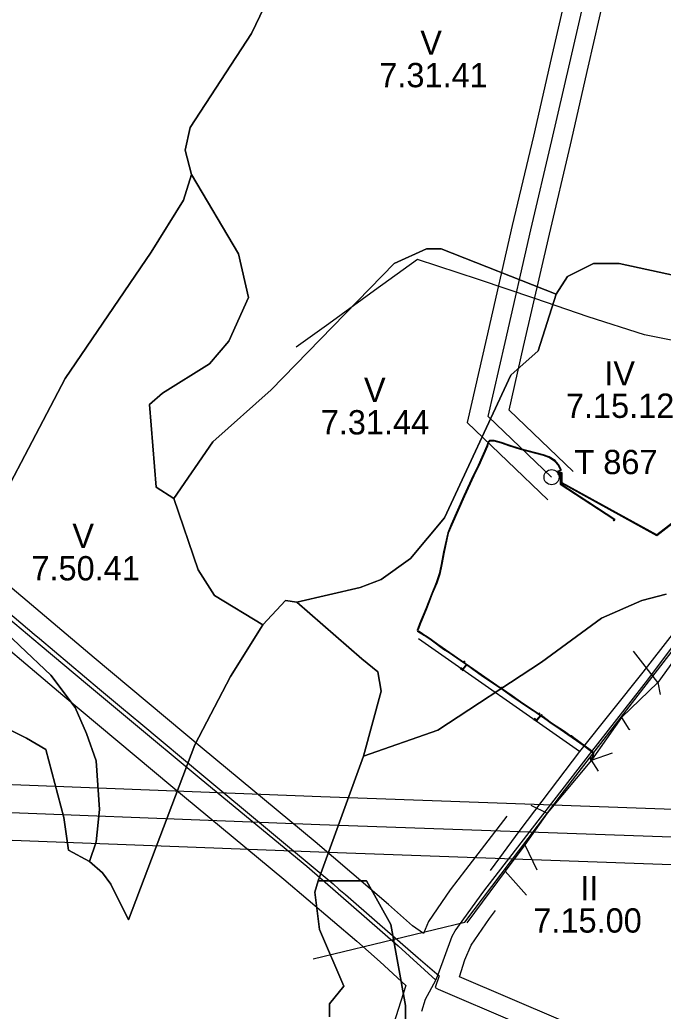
# Model space of a CAD drawing. Extents: x -694504 to -690518, y -983661 to -978958.
# Drawn here: x -692818 to -692421, y -982051 to -981439 of the extents above; entities that cross this region are included whole.
import ezdxf

# ---------------------------------------------------------------- set-up
doc = ezdxf.new("R2010")
doc.units = 0
for name, color, linetype in [('BPEJ', 7, 'Continuous'), ('kabelové a venkovní rozvody telefonu', 7, 'Continuous'), ('kanalizace', 7, 'Continuous'), ('ochranné pásmo silnic', 7, 'Continuous'), ('ochranné pásmo vedení', 7, 'Continuous'), ('PŘÍRODNÍ PARK JEŠTĚD', 7, 'Continuous'), ('trafostanice', 7, 'Continuous'), ('třídy přednosti v ochraně ZP', 7, 'Continuous'), ('vedení NN', 7, 'Continuous'), ('vedení VN 35kV', 7, 'Continuous'), ('vedení VVN 110kV', 7, 'Continuous'), ('vodovodní řad', 7, 'Continuous')]:
    doc.layers.add(name, color=color, linetype=linetype)

msp = doc.modelspace()

# ---------------------------------------------------------------- linework, layer by layer
at = {"layer": 'BPEJ'}
for points in [[(-692662.4, -981420.81), (-692675.4, -981447.81), (-692713.4, -981505.81), (-692716.4, -981519.81), (-692712.4, -981534.81), (-692717.4, -981550.81), (-692737.4, -981582.81), (-692790.4, -981660.81), (-692849.4, -981772.81)], [(-692374.4, -981605.81), (-692448.4, -981589.81), (-692464.4, -981589.81), (-692480.4, -981597.81), (-692487.4, -981608.81), (-692558.4, -981580.81), (-692567.4, -981580.81), (-692587.4, -981589.81), (-692663.4, -981667.81), (-692699.4, -981699.81), (-692723.4, -981734.81), (-692734.4, -981727.81), (-692738.4, -981676.81), (-692730.4, -981669.81), (-692701.4, -981651.81), (-692689.4, -981637.81), (-692677.4, -981610.81), (-692683.4, -981583.81), (-692712.4, -981534.81), (-692716.4, -981519.81), (-692713.4, -981505.81), (-692675.4, -981447.81), (-692662.4, -981420.81)], [(-692849.4, -981772.81), (-692790.4, -981660.81), (-692737.4, -981582.81), (-692717.4, -981550.81), (-692712.4, -981534.81), (-692683.4, -981583.81), (-692677.4, -981610.81), (-692689.4, -981637.81), (-692701.4, -981651.81), (-692730.4, -981669.81), (-692738.4, -981676.81), (-692734.4, -981727.81), (-692723.4, -981734.81), (-692723.4, -981734.81), (-692708.4, -981778.81), (-692698.4, -981794.81), (-692668.4, -981812.81), (-692688.4, -981844.81), (-692710.4, -981886.81), (-692751.4, -981994.81), (-692762.4, -981972.81), (-692767.4, -981965.81), (-692775.4, -981958.81), (-692771.4, -981946.81), (-692769.4, -981926.81), (-692771.4, -981896.81), (-692777.4, -981879.81), (-692784.4, -981863.81), (-692799.4, -981843.81), (-692818.4, -981825.81), (-692838.4, -981806.81)], [(-692419.4, -981793.81), (-692434.4, -981797.81), (-692459.4, -981808.81), (-692496.4, -981835.81), (-692560.4, -981877.81), (-692606.4, -981893.81), (-692595.4, -981853.81), (-692597.4, -981841.81), (-692607.4, -981833.81), (-692647.4, -981798.81), (-692608.4, -981789.81), (-692595.4, -981784.81), (-692577.4, -981771.81), (-692556.4, -981746.81), (-692515.4, -981658.81), (-692498.4, -981643.81), (-692487.4, -981608.81), (-692480.4, -981597.81), (-692464.4, -981589.81), (-692448.4, -981589.81), (-692374.4, -981605.81)], [(-692836.4, -981871.81), (-692814.4, -981882.81), (-692802.4, -981889.81), (-692791.4, -981931.81), (-692788.4, -981951.81), (-692775.4, -981958.81), (-692767.4, -981965.81), (-692762.4, -981972.81), (-692751.4, -981994.81), (-692710.4, -981886.81), (-692688.4, -981844.81), (-692668.4, -981812.81), (-692654.4, -981797.81), (-692647.4, -981798.81), (-692647.4, -981798.81), (-692607.4, -981833.81), (-692597.4, -981841.81), (-692595.4, -981853.81), (-692606.4, -981893.81), (-692634.4, -981970.81), (-692636.4, -981977.81), (-692633.4, -982000.81), (-692618.4, -982035.81), (-692627.4, -982046.81), (-692627.4, -982054.81)], [(-692580.4, -982071.81), (-692580.4, -982047.81), (-692589.4, -981997.81), (-692604.4, -981970.81), (-692634.4, -981970.81), (-692606.4, -981893.81), (-692560.4, -981877.81), (-692496.4, -981835.81), (-692459.4, -981808.81), (-692434.4, -981797.81), (-692419.4, -981793.81)], [(-692838.4, -981806.81), (-692818.4, -981825.81), (-692799.4, -981843.81), (-692784.4, -981863.81), (-692777.4, -981879.81), (-692771.4, -981896.81), (-692769.4, -981926.81), (-692771.4, -981946.81), (-692775.4, -981958.81), (-692788.4, -981951.81), (-692791.4, -981931.81), (-692802.4, -981889.81), (-692814.4, -981882.81), (-692836.4, -981871.81)], [(-692627.4, -982054.81), (-692627.4, -982046.81), (-692618.4, -982035.81), (-692633.4, -982000.81), (-692636.4, -981977.81), (-692634.4, -981970.81), (-692604.4, -981970.81), (-692589.4, -981997.81), (-692580.4, -982047.81), (-692580.4, -982071.81)]]:
    msp.add_lwpolyline(points, dxfattribs=at)
msp.add_lwpolyline([(-692487.4, -981608.81), (-692498.4, -981643.81), (-692515.4, -981658.81), (-692556.4, -981746.81), (-692577.4, -981771.81), (-692595.4, -981784.81), (-692608.4, -981789.81), (-692647.4, -981798.81), (-692654.4, -981797.81), (-692668.4, -981812.81), (-692698.4, -981794.81), (-692708.4, -981778.81), (-692723.4, -981734.81), (-692699.4, -981699.81), (-692663.4, -981667.81), (-692587.4, -981589.81), (-692567.4, -981580.81), (-692558.4, -981580.81), (-692487.4, -981608.81)], close=True, dxfattribs=at)
at = {"layer": 'kabelové a venkovní rozvody telefonu'}
for points in [[(-692841.36, -981795.63), (-692805.92, -981825.24), (-692776.61, -981849.69), (-692752.04, -981870.2), (-692706.49, -981907.98), (-692641.24, -981961.79), (-692585.01, -982011.02), (-692561.58, -982032.11)], [(-692465.37, -981891.04), (-692572.56, -981816.47)], [(-692570.33, -982051.32), (-692568.03, -982043.83), (-692561.58, -982032.11), (-692560.29, -982028.67), (-692551.67, -982004.95), (-692549.66, -982001.78), (-692532.1, -981977.19), (-692501.94, -981938.23), (-692465.37, -981891.04), (-692430.87, -981846.69), (-692415.49, -981826.37)]]:
    msp.add_lwpolyline(points, dxfattribs=at)
at = {"layer": 'kanalizace'}
msp.add_lwpolyline([(-692637.3, -982018.94), (-692543.86, -981996.43), (-692482.24, -981915), (-692389.85, -981795.54), (-692370.2, -981769.76), (-692361.24, -981760.23), (-692369.79, -981750.51), (-692394.74, -981731.55), (-692395.7, -981719.37), (-692377.18, -981674.9), (-692350.54, -981592.69), (-692334.59, -981562.19), (-692328.73, -981553.37), (-692321.59, -981540.53), (-692308.62, -981504.97), (-692303.5, -981486.69), (-692297.29, -981459.54)], dxfattribs=at)
at = {"layer": 'ochranné pásmo silnic'}
for points in [[(-692517.83, -981930.93), (-692543.3, -981964.06), (-692552.86, -981976.39), (-692566.15, -981995.98), (-692569.32, -982003.23), (-692576.03, -981998.55), (-692590.79, -981985.48), (-692636.08, -981946.79), (-692705.99, -981888.88), (-692772.57, -981833.25), (-692831.51, -981783.53)], [(-692849.94, -981807.23), (-692791.86, -981856.22), (-692725.18, -981911.94), (-692655.4, -981969.75), (-692610.48, -982008.12), (-692596.11, -982020.83), (-692580.24, -982035.4), (-692590.95, -982068.93)], [(-692108.37, -982262.8), (-692182.15, -982210.63), (-692260.22, -982164.54), (-692332.9, -982128.59), (-692362.88, -982113.85), (-692384.99, -982099.93), (-692392.66, -982095.86), (-692404.32, -982090.98), (-692484.55, -982056.73), (-692547.02, -982030.01), (-692543.66, -982019.49), (-692539.75, -982010.51), (-692528.56, -981994.02), (-692525.42, -981989.97), (-692524.74, -981989.08)]]:
    msp.add_lwpolyline(points, dxfattribs=at)
at = {"layer": 'ochranné pásmo vedení'}
for points in [[(-692838.35, -981210.45), (-692744.28, -981228.07), (-692659.81, -981243.86), (-692590.14, -981256.55), (-692505.11, -981272.56), (-692449.04, -981282.45), (-692452.47, -981298.46), (-692463.45, -981346.36), (-692476.45, -981402.36), (-692490.45, -981463.37), (-692501.44, -981511.34), (-692514.44, -981566.34), (-692530.37, -981635.87), (-692542.33, -981688.04), (-692492.58, -981735.69)], [(-692476.97, -981718.1), (-692516.45, -981680.3), (-692507.47, -981641.12), (-692491.56, -981571.66), (-692478.56, -981516.66), (-692467.55, -981468.63), (-692453.55, -981407.64), (-692440.55, -981351.64), (-692429.53, -981303.54), (-692425.91, -981286.65), (-692239.14, -981321.55), (-692136.15, -981340.55), (-692063.84, -981354.16), (-692072.29, -981383.76), (-692085.31, -981428.8), (-692098.34, -981475.94), (-692108.32, -981513.84), (-692122.09, -981560.59)], [(-691047.73, -981981.62), (-691271.22, -981973.14), (-691442.35, -981966.56), (-691696.3, -981955.69), (-691917.9, -981947.67), (-692137.38, -981938.64), (-692397.79, -981927.36), (-692632.57, -981919.04), (-692886.88, -981909.19), (-693061.33, -981902.24)], [(-693056.86, -981936.45), (-692888.21, -981943.16), (-692633.83, -981953.01), (-692399.13, -981961.33), (-692138.82, -981972.61), (-691919.21, -981981.65), (-691697.64, -981989.66), (-691443.73, -982000.53), (-691272.52, -982007.11), (-691049.79, -982015.57)]]:
    msp.add_lwpolyline(points, dxfattribs=at)
at = {"layer": 'PŘÍRODNÍ PARK JEŠTĚD'}
msp.add_lwpolyline([(-692840.03, -981792.85), (-692809.64, -981818.5), (-692806.4, -981821.23), (-692769.37, -981852.48), (-692755.7, -981863.86), (-692743.83, -981873.77), (-692704.91, -981906.2), (-692625.09, -981972.72), (-692621.46, -981975.87), (-692617.48, -981979.32), (-692597.92, -981996.27), (-692572.57, -982018.25), (-692559.69, -982029.42), (-692559.69, -982029.42), (-692559.69, -982029.42), (-692562.05, -982036.63), (-692560.3, -982037.73), (-692465.96, -982078.09)], dxfattribs=at)
at = {"layer": 'trafostanice'}
msp.add_ellipse((-692490.22, -981721.68), major_axis=(0, 4.66), ratio=0.997816, dxfattribs=at)
at = {"layer": 'vedení NN'}
for points in [[(-692572.99, -981587.27), (-692599.51, -981606.53), (-692627.65, -981626.97), (-692647.98, -981641.46)], [(-692572.99, -981587.27), (-692599.51, -981606.53), (-692627.65, -981626.97), (-692647.98, -981641.46)], [(-692363.24, -981652.11), (-692399.84, -981640.37), (-692432.85, -981633.91), (-692467.53, -981622.8), (-692500.59, -981611.45), (-692535.39, -981599.72), (-692572.99, -981587.27)], [(-692363.24, -981652.11), (-692399.84, -981640.37), (-692432.85, -981633.91), (-692467.53, -981622.8), (-692500.59, -981611.45), (-692535.39, -981599.72), (-692572.99, -981587.27)], [(-692484.71, -981718.98), (-692485.71, -981718.98), (-692485.7, -981719.74), (-692485.8, -981719.75), (-692485.82, -981718.14), (-692484.38, -981717.56), (-692484.31, -981716.94), (-692485.84, -981713.97), (-692488.07, -981711.49), (-692491.73, -981709.18), (-692495.17, -981707.89), (-692509.34, -981704.24), (-692516.47, -981701.99), (-692521.05, -981700.4), (-692525.63, -981699.07), (-692528.48, -981699.07), (-692529.42, -981699.92), (-692530.21, -981702.43), (-692535.57, -981714.5), (-692538.6, -981720.71), (-692544.37, -981733.31), (-692552.24, -981751), (-692554.35, -981756.14), (-692556.98, -981767.82), (-692558.35, -981775.5), (-692559.62, -981781.44), (-692561.4, -981786.98), (-692564.21, -981793.52), (-692567.85, -981802.88), (-692571.7, -981812.27), (-692572.71, -981815.1), (-692573.11, -981816.04), (-692572.88, -981816.77), (-692568.74, -981819.45), (-692568.18, -981819.58)], [(-692484.71, -981718.98), (-692485.71, -981718.98), (-692485.7, -981719.74), (-692485.8, -981719.75), (-692485.82, -981718.14), (-692484.38, -981717.56), (-692484.31, -981716.94), (-692485.84, -981713.97), (-692488.07, -981711.49), (-692491.73, -981709.18), (-692495.17, -981707.89), (-692509.34, -981704.24), (-692516.47, -981701.99), (-692521.05, -981700.4), (-692525.63, -981699.07), (-692528.48, -981699.07), (-692529.42, -981699.92), (-692530.21, -981702.43), (-692535.57, -981714.5), (-692538.6, -981720.71), (-692544.37, -981733.31), (-692552.24, -981751), (-692554.35, -981756.14), (-692556.98, -981767.82), (-692558.35, -981775.5), (-692559.62, -981781.44), (-692561.4, -981786.98), (-692564.21, -981793.52), (-692567.85, -981802.88), (-692571.7, -981812.27), (-692572.71, -981815.1), (-692573.11, -981816.04), (-692572.88, -981816.77), (-692568.74, -981819.45), (-692568.18, -981819.58)], [(-692484.71, -981718.98), (-692485.31, -981718.99), (-692485.3, -981720.14), (-692486.2, -981720.15), (-692486.22, -981717.88), (-692484.74, -981717.27), (-692484.71, -981717.02), (-692486.18, -981714.21), (-692488.33, -981711.79), (-692491.91, -981709.54), (-692495.29, -981708.27), (-692509.45, -981704.62), (-692516.59, -981702.37), (-692521.17, -981700.78), (-692525.69, -981699.47), (-692528.32, -981699.47), (-692529.08, -981700.14), (-692529.83, -981702.57), (-692535.21, -981714.66), (-692538.24, -981720.88), (-692544.01, -981733.47), (-692551.88, -981751.16), (-692553.97, -981756.26), (-692556.58, -981767.9), (-692557.95, -981775.58), (-692559.24, -981781.54), (-692561.02, -981787.12), (-692563.84, -981793.68), (-692567.47, -981803.02), (-692571.32, -981812.41), (-692572.33, -981815.24), (-692572.69, -981816.06), (-692572.54, -981816.51), (-692568.48, -981819.16), (-692568.18, -981819.58)], [(-692484.71, -981718.98), (-692485.31, -981718.99), (-692485.3, -981720.14), (-692486.2, -981720.15), (-692486.22, -981717.88), (-692484.74, -981717.27), (-692484.71, -981717.02), (-692486.18, -981714.21), (-692488.33, -981711.79), (-692491.91, -981709.54), (-692495.29, -981708.27), (-692509.45, -981704.62), (-692516.59, -981702.37), (-692521.17, -981700.78), (-692525.69, -981699.47), (-692528.32, -981699.47), (-692529.08, -981700.14), (-692529.83, -981702.57), (-692535.21, -981714.66), (-692538.24, -981720.88), (-692544.01, -981733.47), (-692551.88, -981751.16), (-692553.97, -981756.26), (-692556.58, -981767.9), (-692557.95, -981775.58), (-692559.24, -981781.54), (-692561.02, -981787.12), (-692563.84, -981793.68), (-692567.47, -981803.02), (-692571.32, -981812.41), (-692572.33, -981815.24), (-692572.69, -981816.06), (-692572.54, -981816.51), (-692568.48, -981819.16), (-692568.18, -981819.58)], [(-692484.71, -981718.98), (-692484.9, -981718.99), (-692484.89, -981720.06), (-692484.82, -981726.04), (-692451.77, -981747.67), (-692452.18, -981748.34), (-692452.02, -981748.47)], [(-692484.71, -981718.98), (-692484.9, -981718.99), (-692484.89, -981720.06), (-692484.82, -981726.04), (-692451.77, -981747.67), (-692452.18, -981748.34), (-692452.02, -981748.47)], [(-692388.31, -981723.3), (-692387.92, -981723.41), (-692388.27, -981724.54), (-692385.99, -981725.21), (-692386.63, -981727.37), (-692425.21, -981757.37), (-692483.64, -981725.1), (-692483.71, -981718.99), (-692484.71, -981718.98)], [(-692388.31, -981723.3), (-692387.54, -981723.52), (-692387.77, -981724.27), (-692385.46, -981724.94), (-692386.29, -981727.61), (-692425.17, -981757.85), (-692484.03, -981725.35), (-692484.12, -981718.98), (-692484.71, -981718.98)], [(-692484.71, -981718.98), (-692484.5, -981718.98), (-692484.49, -981720.05), (-692484.42, -981725.82), (-692451.22, -981747.55), (-692451.84, -981748.55), (-692452.02, -981748.47)], [(-692388.31, -981723.3), (-692387.92, -981723.41), (-692388.27, -981724.54), (-692385.99, -981725.21), (-692386.63, -981727.37), (-692425.21, -981757.37), (-692483.64, -981725.1), (-692483.71, -981718.99), (-692484.71, -981718.98)], [(-692388.31, -981723.3), (-692387.54, -981723.52), (-692387.77, -981724.27), (-692385.46, -981724.94), (-692386.29, -981727.61), (-692425.17, -981757.85), (-692484.03, -981725.35), (-692484.12, -981718.98), (-692484.71, -981718.98)], [(-692484.71, -981718.98), (-692484.5, -981718.98), (-692484.49, -981720.05), (-692484.42, -981725.82), (-692451.22, -981747.55), (-692451.84, -981748.55), (-692452.02, -981748.47)], [(-692382.45, -981790.51), (-692399.93, -981814.3), (-692424.7, -981848.44)], [(-692382.45, -981790.51), (-692399.93, -981814.3), (-692424.7, -981848.44)], [(-692568.18, -981819.58), (-692567.63, -981819.71), (-692564.39, -981821.9), (-692556.61, -981827.64), (-692553.29, -981829.86), (-692544.62, -981835.88), (-692544.14, -981835.18), (-692543.97, -981835.3)], [(-692464.81, -981895.06), (-692464.68, -981894.91), (-692464.74, -981894.86), (-692464.92, -981894.71), (-692465.08, -981894.59), (-692464.83, -981894.24), (-692464.45, -981892.29), (-692465.29, -981891.32), (-692469.81, -981888), (-692476.68, -981882.83), (-692478.12, -981881.64), (-692479.02, -981881.46), (-692482.46, -981879.08), (-692490.46, -981873.8), (-692496.86, -981869.05), (-692506.27, -981862.87), (-692509.51, -981860.64), (-692514.79, -981857.01), (-692521.35, -981852.38), (-692530.38, -981846.36), (-692533.72, -981844.11), (-692538.88, -981840.33), (-692542.72, -981837.58), (-692544.65, -981836.32), (-692553.51, -981830.2), (-692556.84, -981827.96), (-692564.61, -981822.22), (-692567.85, -981820.05), (-692568.18, -981819.58)], [(-692568.18, -981819.58), (-692567.63, -981819.71), (-692564.39, -981821.9), (-692556.61, -981827.64), (-692553.29, -981829.86), (-692544.62, -981835.88), (-692544.14, -981835.18), (-692543.97, -981835.3)], [(-692464.81, -981895.06), (-692464.68, -981894.91), (-692464.74, -981894.86), (-692464.92, -981894.71), (-692465.08, -981894.59), (-692464.83, -981894.24), (-692464.45, -981892.29), (-692465.29, -981891.32), (-692469.81, -981888), (-692476.68, -981882.83), (-692478.12, -981881.64), (-692479.02, -981881.46), (-692482.46, -981879.08), (-692490.46, -981873.8), (-692496.86, -981869.05), (-692506.27, -981862.87), (-692509.51, -981860.64), (-692514.79, -981857.01), (-692521.35, -981852.38), (-692530.38, -981846.36), (-692533.72, -981844.11), (-692538.88, -981840.33), (-692542.72, -981837.58), (-692544.65, -981836.32), (-692553.51, -981830.2), (-692556.84, -981827.96), (-692564.61, -981822.22), (-692567.85, -981820.05), (-692568.18, -981819.58)], [(-692424.7, -981848.44), (-692439.56, -981829)], [(-692424.7, -981848.44), (-692439.56, -981829)], [(-692543.97, -981835.3), (-692543.77, -981835.44), (-692544.25, -981836.07), (-692542.63, -981837.16), (-692545.16, -981840.21), (-692546.24, -981839.46), (-692546.59, -981839.93), (-692546.42, -981840.04)], [(-692543.97, -981835.3), (-692543.77, -981835.44), (-692544.25, -981836.07), (-692542.63, -981837.16), (-692545.16, -981840.21), (-692546.24, -981839.46), (-692546.59, -981839.93), (-692546.42, -981840.04)], [(-692546.42, -981840.04), (-692546.26, -981840.17), (-692546.15, -981840.02), (-692545.23, -981840.64), (-692545.34, -981840.79), (-692545.01, -981841.02)], [(-692546.42, -981840.04), (-692546.26, -981840.17), (-692546.15, -981840.02), (-692545.23, -981840.64), (-692545.34, -981840.79), (-692545.01, -981841.02)], [(-692545.01, -981841.02), (-692544.66, -981840.55), (-692544.83, -981840.43), (-692542.31, -981837.38), (-692538.64, -981840.01), (-692533.49, -981843.79), (-692530.16, -981846.02), (-692521.4, -981851.88), (-692521, -981851.31), (-692520.83, -981851.43)], [(-692545.01, -981841.02), (-692544.66, -981840.55), (-692544.83, -981840.43), (-692542.31, -981837.38), (-692538.64, -981840.01), (-692533.49, -981843.79), (-692530.16, -981846.02), (-692521.4, -981851.88), (-692521, -981851.31), (-692520.83, -981851.43)], [(-692497.74, -981867.42), (-692497.9, -981867.31), (-692498.19, -981867.7), (-692506.05, -981862.53), (-692509.29, -981860.31), (-692514.55, -981856.69), (-692521.05, -981852.09), (-692520.66, -981851.54), (-692520.83, -981851.43)], [(-692497.74, -981867.42), (-692497.9, -981867.31), (-692498.19, -981867.7), (-692506.05, -981862.53), (-692509.29, -981860.31), (-692514.55, -981856.69), (-692521.05, -981852.09), (-692520.66, -981851.54), (-692520.83, -981851.43)], [(-692424.7, -981848.44), (-692447.05, -981869.92)], [(-692424.7, -981848.44), (-692447.05, -981869.92)], [(-692424.7, -981848.44), (-692423.22, -981855.85)], [(-692424.7, -981848.44), (-692423.22, -981855.85)], [(-692497.74, -981867.42), (-692497.57, -981867.54), (-692497.72, -981867.74), (-692497.36, -981868.18), (-692496.99, -981868.68), (-692499.57, -981871.52), (-692500.71, -981870.73), (-692501.17, -981871.36), (-692501.01, -981871.47)], [(-692497.74, -981867.42), (-692497.57, -981867.54), (-692497.72, -981867.74), (-692497.36, -981868.18), (-692496.99, -981868.68), (-692499.57, -981871.52), (-692500.71, -981870.73), (-692501.17, -981871.36), (-692501.01, -981871.47)], [(-692496.28, -981868.39), (-692496.45, -981868.28), (-692496.71, -981868.64), (-692496.69, -981868.94), (-692499.25, -981871.77), (-692499.03, -981871.93), (-692499.48, -981872.53), (-692499.64, -981872.42)], [(-692496.28, -981868.39), (-692496.45, -981868.28), (-692496.71, -981868.64), (-692496.69, -981868.94), (-692499.25, -981871.77), (-692499.03, -981871.93), (-692499.48, -981872.53), (-692499.64, -981872.42)], [(-692464.81, -981895.06), (-692464.42, -981894.6), (-692464.54, -981894.51), (-692464.45, -981894.39), (-692464.03, -981892.17), (-692465.01, -981891.02), (-692469.57, -981887.68), (-692476.44, -981882.51), (-692477.94, -981881.26), (-692478.86, -981881.08), (-692482.24, -981878.74), (-692490.22, -981873.48), (-692496.4, -981868.88), (-692496.11, -981868.51), (-692496.28, -981868.39)], [(-692464.81, -981895.06), (-692464.42, -981894.6), (-692464.54, -981894.51), (-692464.45, -981894.39), (-692464.03, -981892.17), (-692465.01, -981891.02), (-692469.57, -981887.68), (-692476.44, -981882.51), (-692477.94, -981881.26), (-692478.86, -981881.08), (-692482.24, -981878.74), (-692490.22, -981873.48), (-692496.4, -981868.88), (-692496.11, -981868.51), (-692496.28, -981868.39)], [(-692447.05, -981869.92), (-692465.58, -981896.42)], [(-692447.05, -981869.92), (-692465.58, -981896.42)], [(-692447.05, -981869.92), (-692442.55, -981877.17), (-692441.8, -981877.46)], [(-692447.05, -981869.92), (-692442.55, -981877.17), (-692441.8, -981877.46)], [(-692499.64, -981872.42), (-692499.81, -981872.31), (-692499.59, -981872.01), (-692500.62, -981871.28), (-692500.85, -981871.59), (-692501.01, -981871.47)], [(-692499.64, -981872.42), (-692499.81, -981872.31), (-692499.59, -981872.01), (-692500.62, -981871.28), (-692500.85, -981871.59), (-692501.01, -981871.47)], [(-692464.81, -981895.06), (-692464.94, -981895.22), (-692465.59, -981894.69), (-692466.45, -981895.68), (-692465.58, -981896.42)], [(-692464.81, -981895.06), (-692464.94, -981895.22), (-692465.59, -981894.69), (-692466.45, -981895.68), (-692465.58, -981896.42)], [(-692465.58, -981896.42), (-692452.54, -981891.73)], [(-692465.58, -981896.42), (-692452.54, -981891.73)], [(-692465.58, -981896.42), (-692492.93, -981929.02)], [(-692465.58, -981896.42), (-692492.93, -981929.02)], [(-692461.24, -981903.06), (-692465.58, -981896.42)], [(-692461.24, -981903.06), (-692465.58, -981896.42)], [(-692502.91, -981924.14), (-692492.93, -981929.02)], [(-692502.91, -981924.14), (-692492.93, -981929.02)], [(-692492.93, -981929.02), (-692506.73, -981948.57)], [(-692492.93, -981929.02), (-692506.73, -981948.57)], [(-692506.73, -981948.57), (-692518.88, -981964.86)], [(-692506.73, -981948.57), (-692518.88, -981964.86)], [(-692506.73, -981948.57), (-692499.32, -981963.93)], [(-692506.73, -981948.57), (-692499.32, -981963.93)], [(-692518.88, -981964.86), (-692542.61, -981996.84)], [(-692518.88, -981964.86), (-692542.61, -981996.84)], [(-692518.23, -981963.78), (-692518.88, -981964.86)], [(-692518.23, -981963.78), (-692518.88, -981964.86)], [(-692505.59, -981979.67), (-692518.88, -981964.86)], [(-692505.59, -981979.67), (-692518.88, -981964.86)]]:
    msp.add_lwpolyline(points, dxfattribs=at)
at = {"layer": 'vedení VN 35kV'}
msp.add_lwpolyline([(-692490.22, -981721.68), (-692529.39, -981684.17), (-692518.92, -981638.49), (-692503, -981569), (-692490, -981514), (-692479, -981466), (-692465, -981405), (-692452, -981349), (-692441, -981301), (-692435, -981273)], dxfattribs=at)
at = {"layer": 'vedení VVN 110kV'}
msp.add_lwpolyline([(-693059.68, -981919.32), (-692887.54, -981926.17), (-692633.2, -981936.03), (-692398.46, -981944.34), (-692138.1, -981955.62), (-691918.56, -981964.66), (-691696.97, -981972.67), (-691443.04, -981983.54), (-691271.87, -981990.13), (-691048.23, -981998.61)], dxfattribs=at)
at = {"layer": 'vodovodní řad'}
for points in [[(-692399.12, -981797.49), (-692433.91, -981841.96), (-692473.05, -981891.06), (-692509.84, -981939.46), (-692528.18, -981964.44)], [(-692473.05, -981891.06), (-692572.4, -981821.42)]]:
    msp.add_lwpolyline(points, dxfattribs=at)

# ---------------------------------------------------------------- texts
at = {"layer": 'trafostanice'}
msp.add_text('T 867', height=15, dxfattribs=at).set_placement((-692476.1, -981719.84))
at = {"layer": 'třídy přednosti v ochraně ZP'}
for s, p in [('V', (-692571.27, -981461.04)), ('7.31.41', (-692596.55, -981481.04)), ('IV', (-692457.64, -981665.11)), ('V', (-692606.02, -981675.33)), ('7.15.12', (-692481.36, -981685.11)), ('7.31.44', (-692632.71, -981695.33)), ('V', (-692786.06, -981765.41)), ('7.50.41', (-692811.33, -981785.41)), ('II', (-692472.55, -981982.78)), ('7.15.00', (-692501.45, -982002.78))]:
    msp.add_text(s, height=15, dxfattribs=at).set_placement(p)

doc.saveas('drawing.dxf')
